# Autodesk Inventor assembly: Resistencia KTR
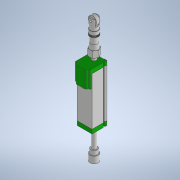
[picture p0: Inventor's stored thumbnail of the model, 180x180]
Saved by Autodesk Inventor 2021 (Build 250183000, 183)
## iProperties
Created: 2021-02
Part Number: Resistencia KTR
Document SubType Name: Assembly
Designer: ATOUZA
Author: ATOUZA
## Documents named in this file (3)
- D:\01 Paralaia\Grupos de Traballo\GT Maquetas\CAD 3D\E_Medida\ResistenciaKTR\Resistencia KTR.iam
- D:\01 Paralaia\Grupos de Traballo\GT Maquetas\CAD 3D\E_Medida\ResistenciaKTR\CuerpoKTR.ipt
- D:\01 Paralaia\Grupos de Traballo\GT Maquetas\CAD 3D\E_Medida\Barilla.ipt
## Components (2 placed, 2 different names)
1. CuerpoKTR:1 — Insertar:1
2. Barilla:1 — Insertar:1
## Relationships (1: Insert 1)
- Insertar:1: CuerpoKTR:1 ↔ Barilla:1
